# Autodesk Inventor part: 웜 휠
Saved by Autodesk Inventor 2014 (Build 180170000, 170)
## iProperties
Created: 2025-06
Part Number: 웜 휠
Material: 일반
Document SubType Name: Modeling
Designer: dg
Density: 1 g/cm^3
Appearance: 기본값
Author: dg
Author: jhkim
Creation Date: 2025-05-23
Sending System: Autodesk Inventor 2026
Preprocessor: ST-DEVELOPER v20.1
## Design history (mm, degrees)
node "웜 휠1"
body "Solid1"
node "기준1"
